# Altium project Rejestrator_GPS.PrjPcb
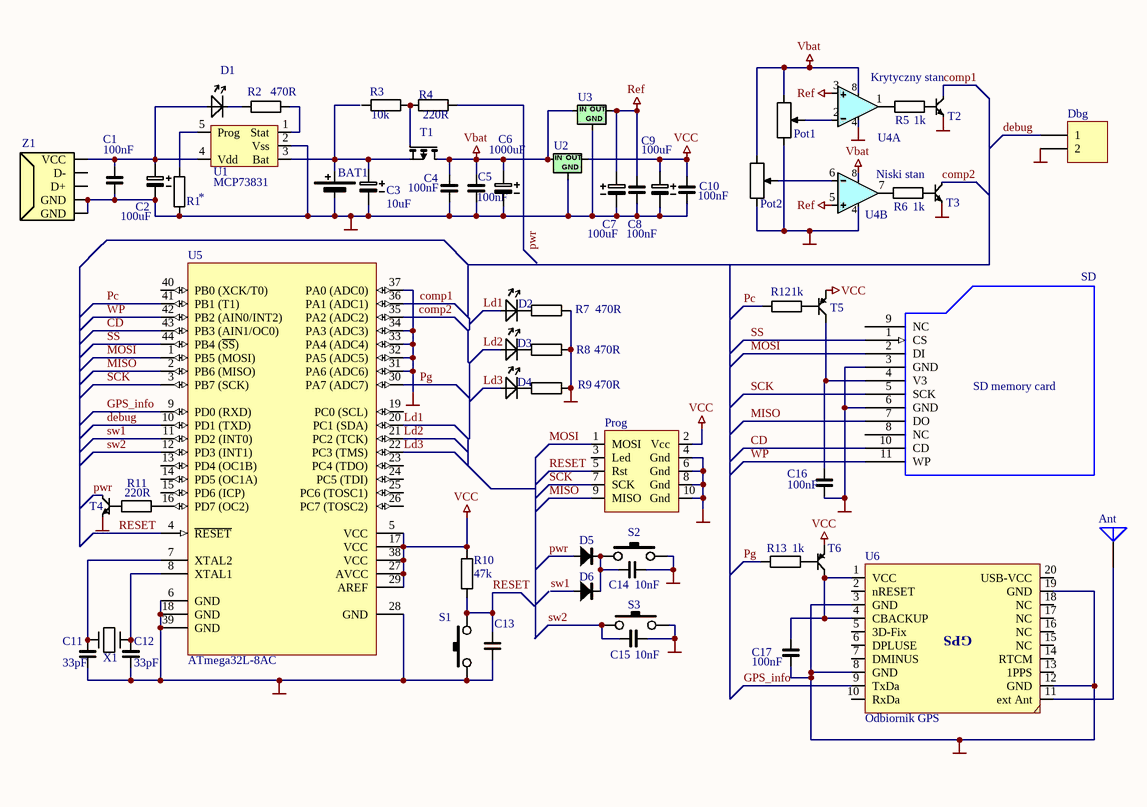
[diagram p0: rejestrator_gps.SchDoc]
1 sheet, 60 parts. Net scope: global (net labels, ports and power ports of the same name join across sheets).
Board file: pcb_new1.PcbDoc

## Sheet rejestrator_gps.SchDoc
size A4; DrawnBy: Radosław Krawczyk

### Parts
Ant  Antenna  [ipx]  (value not drawn)
BAT1  BAT  [jmp2]  (value not drawn)
C1  100nF  [0603]
C2  100uF  [kondel_smd]
C3  10uF  [C el./2.5mm]
C4  100nF  [0603]
C5  100nF  [0603]
C6  1000uF  [C el./2.5mm]
C7  100uF  [C el./2.5mm]
C8  100nF  [0603]
C9  100uF  [C el./2.5mm]
C10  100nF  [0603]
C11  33pF  [1206]
C12  33pF  [1206]
C13  100nF  [0603]  (value not drawn)
C14  10nF  [0603]
C15  10nF  [0603]
C16  100nF  [0603]
C17  100nF  [0603]
D1  LED0  [LED 3 MM]  (value not drawn)
D2  LED0  [LED 3 MM]  (value not drawn)
D3  LED0  [LED 3 MM]  (value not drawn)
D4  LED0  [LED 3 MM]  (value not drawn)
D5  D  [D2]  (value not drawn)
D6  D  [D2]  (value not drawn)
Dbg  Header 2  [HDR1X2]  (value not drawn)
Pot1  RPOT  [heli]  (value not drawn)
Pot2  RPOT  [heli]  (value not drawn)
Prog  AVR_PROG  [hdr2x5]  (value not drawn)
R1  *  [1206]
R2  470R  [1206]
R3  10k  [1206]
R4  220R  [1206]
R5  1k  [1206]
R6  1k  [1206]
R7  470R  [1206]
R8  470R  [1206]
R9  470R  [1206]
R10  47k  [1206]
R11  220R  [1206]
R12  1k  [1206]
R13  1k  [1206]
S1  MSWITCH  [MSWITCH]  (value not drawn)
S2  MSWITCH  [MSWITCH]  (value not drawn)
S3  MSWITCH  [MSWITCH]  (value not drawn)
SD  SD-MMC  [SD-MMC]  (value not drawn)
T1  IRF7416 PMOS  [IRF7416]  (value not drawn)
T2  BC548B  [sot-23 rk]  (value not drawn)
T3  BC548B  [sot-23 rk]  (value not drawn)
T4  (no value)  [sot-23 rk]
T5  BC857 {PNP}  [SOT95P240-3M]  (value not drawn)
T6  BC857 {PNP}  [SOT95P240-3M]  (value not drawn)
U1  MCP73831  [sot23-5an]
U2  MCP1700  [SOT95P240-3M]  (value not drawn)
U3  MCP1700  [SOT95P240-3M]  (value not drawn)
U4  LM358  [SOIC127P600-8BL]  (value not drawn)  (parts A,B of 2)
U5  ATmega32L-8AC  [TQFP44-08]
U6  Odbiornik GPS  [GPS]
X1  X  [X]  (value not drawn)
Z1  USB_con  [USB_B]  (value not drawn)

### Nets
Gnd: BAT1.2 C1.2 C2.2 C3.2 C4.2 C5.2 C6.2 C7.2 C8.2 C9.2 C10.2 C11.2 C12.2 C13.2 C14.1 C15.1 C16.2 C17.1 Dbg.2 Pot1.1(TOP) Pot2.1(TOP) Prog.4(Gnd) Prog.6(Gnd) Prog.8(Gnd) Prog.10(Gnd) R1.1(TOP) R7.2(BOT) R8.1(TOP) R9.1(TOP) S1.1 S2.2 S3.2 SD.3(GND) SD.6(GND) T2.1(C) T3.1(C) T4.1 U1.2(Vss) U2.1(GND) U3.1(GND) U4.4(VCC-) U5.6(GND) U5.18(GND) U5.28(GND) U5.31(PA6_(ADC6)) U5.32(PA5_(ADC5)) U5.33(PA4_(ADC4)) U5.34(PA3_(ADC3)) U5.37(PA0_(ADC0)) U5.39(GND) U6.3(GND) U6.8(GND) U6.12(GND) U6.19(GND) Z1.4(GND) Z1.5(GND)
Ref: C7.1 C8.1 U3.2(VOUT) U4.3 U4.5(+)
Vbat: C4.1 C5.1 C6.1 Pot1.2(BOT) Pot2.2(BOT) T1.5(D) U2.3(VIN) U3.3(VIN) U4.8(VCC+)
VCC: C9.1 C10.1 Prog.2(Vcc) R10.1(TOP) T5.2(C) T6.2(C) U2.2(VOUT) U5.5(VCC) U5.17(VCC) U5.27(AVCC) U5.29(AREF) U5.38(VCC)
CD: SD.10(CD) U5.43(PB3_(AIN1/OC0))
comp1: T2.3(E) U5.36(PA1_(ADC1))
comp2: T3.3(E) U5.35(PA2_(ADC2))
debug: Dbg.1 U5.10(PD1_(TXD))
GPS_info: U5.9(PD0_(RXD)) U6.9(TxDa)
Ld1: D2.1(K) U5.20(PC1_(SDA))
Ld2: D3.1(K) U5.21(PC2_(TCK))
Ld3: D4.1(K) U5.22(PC3_(TMS))
MISO: Prog.9(MISO) SD.7(DO) U5.2(PB6_(MISO))
MOSI: Prog.1(MOSI) SD.2(DI) U5.1(PB5_(MOSI))
Pc: R12.1(TOP) U5.41(PB1_(T1))
Pg: R13.1(TOP) U5.30(PA7_(ADC7))
pwr: D5.1(A) R4.2(BOT) T4.3
RESET: C13.1 Prog.5(Rst) R10.2(BOT) S1.2 U5.4(~{RESET})
SCK: Prog.7(SCK) SD.5(SCK) U5.3(PB7_(SCK))
SS: SD.1(CS) U5.44(PB4_(~{SS}))
sw1: D6.1(A) U5.11(PD2_(INT0))
sw2: C15.2 S3.1 U5.12(PD3_(INT1))
WP: SD.11(WP) U5.42(PB2_(AIN0/INT2))
NetAnt_1: Ant.1(A) U6.11(ext_Ant)
NetBAT1_1: BAT1.1 C3.1 T1.1(S) U1.3(Bat)
NetC1_1: C1.1 C2.1 D1.1(K) U1.4(Vdd) Z1.1(VCC)
NetC11_1: C11.1 U5.7(XTAL2) X1.1
NetC12_1: C12.1 U5.8(XTAL1) X1.2
NetC14_2: C14.2 D5.2(K) D6.2(K) S2.1
NetC16_1: C16.1 SD.4(V3) T5.3(E)
NetC17_2: C17.2 T6.3(E) U6.1(VCC) U6.4(CBACKUP)
NetD1_2: D1.2(A) R2.1(TOP)
NetD2_2: D2.2(A) R7.1(TOP)
NetD3_2: D3.2(A) R8.2(BOT)
NetD4_2: D4.2(A) R9.2(BOT)
NetPot1_3: Pot1.3(TAP) U4.2
NetPot2_3: Pot2.3(TAP) U4.6(-)
NetR1_2: R1.2(BOT) U1.5(Prog)
NetR2_2: R2.2(BOT) U1.1(Stat)
NetR3_2: R3.2(BOT) R4.1(TOP) T1.4(G)
NetR5_1: R5.1(TOP) U4.1
NetR5_2: R5.2(BOT) T2.2(B)
NetR6_1: R6.1(TOP) U4.7
NetR6_2: R6.2(BOT) T3.2(B)
NetR11_1: R11.1(TOP) T4.2
NetR11_2: R11.2(BOT) U5.16(PD7_(OC2))
NetR12_2: R12.2(BOT) T5.1(B)
NetR13_2: R13.2(BOT) T6.1(B)

Not connected (* = marked no-connect by the designer): Prog 3(Led); R3 1(TOP); SD 8(NC) 9(NC); U5 13(PD4_(OC1B)) 14(PD5_(OC1A)) 15(PD6_(ICP)) 19(PC0_(SCL)) 23(PC4_(TDO)) 24(PC5_(TDI)) 25(PC6_(TOSC1)) 26(PC7_(TOSC2)) 40(PB0_(XCK/T0)); U6 2(nRESET) 5(3D-Fix) 6(DPLUSE) 7(DMINUS) 10(RxDa) 13(1PPS) 14(RTCM) 15(NC) 16(NC) 17(NC) 18(NC) 20(USB-VCC); Z1 2(D-) 3(D+)

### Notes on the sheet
- Krytyczny stan
- Niski stan

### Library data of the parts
Ant = Antenna: Generic Antenna
BAT1 = BAT: Voltage Source - bateria i zasilacz
C1 C4 C5 C8 C10-C17 = CAP: Condenstor
C2 C3 C6 C7 C9 = CAP2: kONDENSATOR ELEKTROLITYCZNY
D1-D4 = LED0: dioda elektroluminescencyjna LED
D5 D6 = D: Dioda
Dbg = Header 2: Header, 2-Pin
Pot1 Pot2 = RPOT: Potencjometr
R1-R13 = RES: Rezystor
T2 T3 = BC548B: Tranzystor NPN
T4 = BC547B: Tranzystor NPN
U4 = LM358: Low-Noise JFET-Input Operational Amplifiers
U5 = ATmega32L-8AC: 8-Bit AVR Microcontroller with 32K Bytes of In-System Programmable Flash Memory
X1 = X: Kwarc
